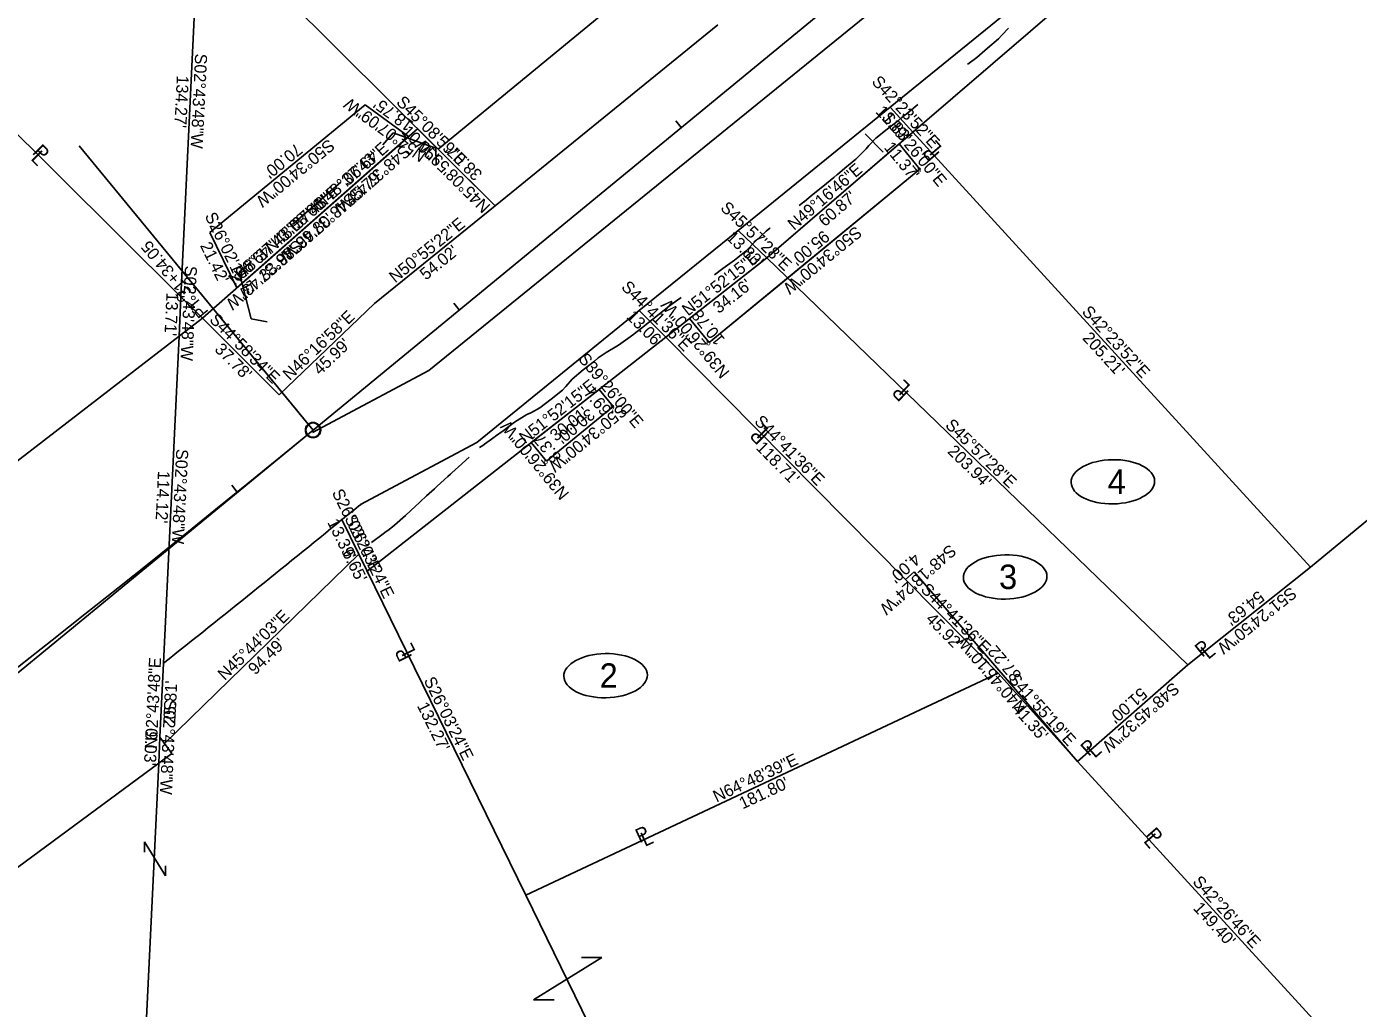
# Model space of a CAD drawing. Extents: x 1145508 to 2262867, y -3126236 to 2021677.
# Drawn here: x 1146740.3 to 1147204, y 2016667.2 to 2017009.2 of the extents above; entities that cross this region are included whole.
import ezdxf

# ---------------------------------------------------------------- set-up
doc = ezdxf.new("R2010")
doc.units = 0
for name, color, linetype in [('Default', 7, 'Continuous'), ('DSN_RDWY_Alignment', 7, 'Continuous'), ('DSN_RDWY_Alignment Annotation', 7, 'Continuous'), ('DSN_RDWY_Const Limits', 7, 'Continuous'), ('DSN_ROW_Annotation', 7, 'Continuous'), ('DSN_ROW_Esmnt', 7, 'Continuous'), ('DSN_ROW_Line', 7, 'Continuous'), ('DSN_ROW_Line-Annotation', 7, 'Continuous'), ('DSN_ROW_Prop-Line', 7, 'Continuous'), ('DSN_ROW_Prop-Line-Annotation', 7, 'Continuous'), ('DSN_ROW_Temp-Esmnt', 7, 'Continuous'), ('E_Const Align', 7, 'Continuous'), ('EX_PRIMARY_CTL', 7, 'Continuous'), ('EX_ROW', 7, 'Continuous'), ('EX_ROW_ANNOT', 7, 'Continuous'), ('EX_SECTION', 7, 'Continuous'), ('EX_SIGN', 7, 'Continuous')]:
    doc.layers.add(name, color=color, linetype=linetype)

msp = doc.modelspace()

# ---------------------------------------------------------------- linework, layer by layer
at = {"layer": 'Default'}
for p, q in [((1147109.89, 2017075.82), (1146880.36, 2016889.44)), ((1146880.36, 2016889.44), (1146839.86, 2016867.83))]:
    msp.add_line(p, q, dxfattribs=at)
at = {"layer": 'DSN_RDWY_Alignment'}
msp.add_line((1146478.89, 2016571.64), (1146840, 2016868.61), dxfattribs=at)
msp.add_lwpolyline([(1146840, 2016868.61), (1146758.6, 2016967.6)], dxfattribs=at)
msp.add_circle((1146840, 2016868.61), 2.5, dxfattribs=at)
at = {"layer": 'DSN_RDWY_Alignment Annotation'}
for p, q in [((1146966.27, 2016976.34), (1146968.17, 2016974.02)), ((1146838.31, 2016870.68), (1146782.84, 2016938.13)), ((1146782.84, 2016938.13), (1146782.84, 2016938.13)), ((1146889.03, 2016912.82), (1146890.94, 2016910.5)), ((1146840, 2016868.61), (1146840, 2016868.61)), ((1146811.74, 2016849.39), (1146813.64, 2016847.06))]:
    msp.add_line(p, q, dxfattribs=at)
msp.add_circle((1146840, 2016868.61), 2.67, dxfattribs=at)
at = {"layer": 'DSN_RDWY_Const Limits'}
for points in [[(1147067.91, 2016996.1), (1147068.3, 2016996.37), (1147068.41, 2016996.45), (1147071.13, 2016998.39), (1147074.88, 2017001.7), (1147078.68, 2017004.95), (1147079.75, 2017006.08), (1147079.84, 2017006.17), (1147082.15, 2017008.6)], [(1147009.31, 2016946.85), (1147009.68, 2016947.16), (1147010.91, 2016948.15), (1147010.96, 2016948.19), (1147013.56, 2016950.31), (1147017.45, 2016953.46), (1147021.31, 2016956.63), (1147022.52, 2016957.64), (1147022.57, 2016957.69), (1147025.15, 2016959.84), (1147028.99, 2016963.04), (1147032.53, 2016966.6), (1147033.54, 2016967.76), (1147033.67, 2016967.91), (1147035.94, 2016970.33), (1147039.86, 2016973.44), (1147043.83, 2016976.48), (1147045, 2016977.58), (1147045.01, 2016977.58), (1147047.71, 2016979.64), (1147050.59, 2016982.09)], [(1146979.79, 2016922.75), (1146982.68, 2016924.89), (1146984.29, 2016926.08), (1146985.94, 2016927.3), (1146986.71, 2016927.87), (1146987.94, 2016928.78), (1146988.07, 2016928.87), (1146990.67, 2016930.92), (1146994.15, 2016934.56), (1146997.82, 2016937.96), (1146999, 2016938.99), (1146999.08, 2016939.06)], [(1146898.02, 2016862.52), (1146899.08, 2016863.29), (1146899.58, 2016863.64), (1146899.59, 2016863.65), (1146899.65, 2016863.69), (1146902.09, 2016865.45), (1146903.07, 2016866.17), (1146903.3, 2016866.33), (1146903.37, 2016866.38), (1146903.52, 2016866.49), (1146906.15, 2016868.39), (1146910.12, 2016871.43), (1146914.44, 2016874.04), (1146915.88, 2016874.68), (1146916.11, 2016874.77), (1146919.02, 2016876.36), (1146922.95, 2016879.44), (1146926.87, 2016882.54), (1146927.89, 2016883.68), (1146928.05, 2016883.86), (1146930.25, 2016886.32), (1146934.02, 2016889.59), (1146937.95, 2016892.69), (1146939.16, 2016893.67), (1146939.27, 2016893.76), (1146942.01, 2016895.63), (1146946.35, 2016898.22), (1146950.46, 2016901.09), (1146951.67, 2016902.01), (1146951.83, 2016902.14), (1146954.41, 2016904.17), (1146958.33, 2016907.26), (1146962.24, 2016910.38), (1146963.43, 2016911.33), (1146963.59, 2016911.45), (1146965.39, 2016912.85), (1146966.2, 2016913.44), (1146968.22, 2016914.8)], [(1146860.37, 2016829.48), (1146864.43, 2016832.47), (1146865.49, 2016833.26), (1146866.06, 2016833.69), (1146867.71, 2016834.91), (1146867.71, 2016834.92), (1146868.42, 2016835.54), (1146872.15, 2016838.88), (1146875.83, 2016842.28), (1146876.79, 2016843.16), (1146877.29, 2016843.62), (1146879.52, 2016845.67), (1146882.3, 2016848.2), (1146883.22, 2016849.04), (1146886.92, 2016852.41), (1146887.88, 2016853.29), (1146888.36, 2016853.73), (1146890.62, 2016855.78), (1146894.32, 2016859.16)]]:
    msp.add_lwpolyline(points, dxfattribs=at)
at = {"layer": 'DSN_ROW_Esmnt'}
for p, q in [((1146876.39, 2016973.63), (1146801.5, 2016907.67)), ((1146876.39, 2016973.63), (1146838.94, 2016940.65)), ((1146903.38, 2016946.78), (1146876.39, 2016973.63)), ((1146861.44, 2016912.73), (1146903.38, 2016946.78)), ((1146838.94, 2016940.65), (1146801.5, 2016907.67)), ((1146828.2, 2016880.94), (1146861.44, 2016912.73)), ((1146801.5, 2016907.67), (1146828.2, 2016880.94))]:
    msp.add_line(p, q, dxfattribs=at)
at = {"layer": 'DSN_ROW_Line'}
for p, q in [((1146883.52, 2016966.54), (1147084.43, 2017131.78)), ((1147048.88, 2016972.43), (1147200.36, 2017102.81)), ((1146801.5, 2016907.67), (1146876.39, 2016973.63)), ((1146876.39, 2016973.63), (1146883.52, 2016966.54)), ((1146997.95, 2016928.59), (1147048.88, 2016972.43)), ((1147051.3, 2016959.52), (1147044.08, 2016968.3)), ((1147004.92, 2016921.37), (1147051.3, 2016959.52)), ((1146962.79, 2016900.99), (1146997.95, 2016928.59)), ((1146977.93, 2016899.18), (1147004.92, 2016921.37)), ((1146971.08, 2016907.5), (1146977.93, 2016899.18)), ((1146858.89, 2016819.44), (1146962.79, 2016900.99)), ((1146944.49, 2016876.86), (1146939.61, 2016882.8)), ((1146921.32, 2016857.81), (1146944.49, 2016876.86)), ((1146916.01, 2016864.27), (1146921.32, 2016857.81)), ((1146788.31, 2016759.46), (1146855.97, 2016825.41)), ((1146855.97, 2016825.41), (1146858.89, 2016819.44))]:
    msp.add_line(p, q, dxfattribs=at)
at = {"layer": 'DSN_ROW_Line-Annotation'}
for centre in [(1147118.48, 2016850.62), (1147080.98, 2016817.47), (1146941.86, 2016783.08)]:
    msp.add_ellipse(centre, major_axis=(14.54, 0.23), ratio=0.529773, dxfattribs=at)
at = {"layer": 'DSN_ROW_Prop-Line'}
for p, q in [((1147040.91, 2016981.16), (1147048.88, 2016972.43)), ((1147048.88, 2016972.43), (1147187.25, 2016820.88)), ((1146988.01, 2016938.21), (1146997.95, 2016928.59)), ((1146997.95, 2016928.59), (1147144.55, 2016786.81)), ((1146953.61, 2016910.27), (1146962.79, 2016900.99)), ((1146962.79, 2016900.99), (1147046.28, 2016816.6)), ((1147187.25, 2016820.88), (1147252.87, 2016874.96)), ((1146850.09, 2016837.44), (1146855.97, 2016825.41)), ((1146855.97, 2016825.41), (1146914.07, 2016706.59)), ((1147049.27, 2016819.26), (1147046.28, 2016816.6)), ((1147106.2, 2016753.19), (1147049.27, 2016819.26)), ((1147187.25, 2016820.88), (1147144.55, 2016786.81)), ((1147046.28, 2016816.6), (1147078.57, 2016783.96)), ((1147144.55, 2016786.81), (1147106.2, 2016753.19)), ((1146914.07, 2016706.59), (1147078.57, 2016783.96)), ((1147078.57, 2016783.96), (1147106.2, 2016753.19)), ((1147106.2, 2016753.19), (1147207.03, 2016642.95)), ((1146914.07, 2016706.59), (1146993.63, 2016543.86))]:
    msp.add_line(p, q, dxfattribs=at)
at = {"layer": 'DSN_ROW_Prop-Line-Annotation'}
for p, q in [((1146781.31, 2016721.64), (1146781.31, 2016725.19)), ((1146781.31, 2016725.19), (1146788.69, 2016713.34)), ((1146788.69, 2016713.34), (1146788.69, 2016716.88)), ((1146940.52, 2016684.89), (1146916.81, 2016670.12)), ((1146933.43, 2016684.89), (1146940.52, 2016684.89)), ((1146916.81, 2016670.12), (1146923.91, 2016670.12))]:
    msp.add_line(p, q, dxfattribs=at)
at = {"layer": 'DSN_ROW_Temp-Esmnt'}
for p, q in [((1146858.11, 2016981.9), (1146804.04, 2016937.44)), ((1146873.3, 2016970.91), (1146858.11, 2016981.9)), ((1146813.45, 2016918.2), (1146873.3, 2016970.91)), ((1146838.94, 2016940.65), (1146873.3, 2016970.91)), ((1146997.95, 2016928.59), (1147044.08, 2016968.3)), ((1147044.08, 2016968.3), (1147051.3, 2016959.52)), ((1147051.3, 2016959.52), (1146977.93, 2016899.18)), ((1146813.45, 2016918.2), (1146838.94, 2016940.65)), ((1146804.04, 2016937.44), (1146813.45, 2016918.2)), ((1146971.08, 2016907.5), (1146997.95, 2016928.59)), ((1146977.93, 2016899.18), (1146971.08, 2016907.5)), ((1146916.01, 2016864.27), (1146939.61, 2016882.8)), ((1146939.61, 2016882.8), (1146944.49, 2016876.86)), ((1146944.49, 2016876.86), (1146921.32, 2016857.81)), ((1146921.32, 2016857.81), (1146916.01, 2016864.27))]:
    msp.add_line(p, q, dxfattribs=at)
at = {"layer": 'E_Const Align'}
msp.add_line((1146840, 2016868.61), (1147825.51, 2017679.08), dxfattribs=at)
msp.add_arc((1143200.69, 2021293.93), 5729.58, 300.103113, 309.43332, dxfattribs=at)
msp.add_arc((1143200.69, 2021293.93), 5729.58, 300.103113, 309.43332, dxfattribs=at)
at = {"layer": 'EX_ROW'}
for p, q in [((1147040.91, 2016981.16), (1147128.8, 2017052.53)), ((1146800.42, 2017049.21), (1146903.38, 2016946.78)), ((1146903.38, 2016946.78), (1146980.95, 2017009.77)), ((1146700.32, 2017008.19), (1146794.02, 2016915.09)), ((1147040.91, 2016981.16), (1146988.01, 2016938.21)), ((1146861.44, 2016912.73), (1146903.38, 2016946.78)), ((1146988.01, 2016938.21), (1146953.61, 2016910.27)), ((1146794.02, 2016915.09), (1146801.5, 2016907.67)), ((1146828.2, 2016880.94), (1146861.44, 2016912.73)), ((1146793.37, 2016901.4), (1146801.5, 2016907.67)), ((1146801.5, 2016907.67), (1146828.2, 2016880.94)), ((1146953.61, 2016910.27), (1146897.03, 2016864.33)), ((1146721.65, 2016846.02), (1146793.37, 2016901.4)), ((1146897.03, 2016864.33), (1146856.59, 2016842.76)), ((1146790.86, 2016756), (1146786.71, 2016761.63)), ((1146786.28, 2016752.61), (1146790.86, 2016756)), ((1146613.11, 2016624.88), (1146786.28, 2016752.61))]:
    msp.add_line(p, q, dxfattribs=at)
for start_param, end_param in [(4.718574, 4.720028), (4.704767, 4.718574)]:
    msp.add_ellipse((1143207.59, 2021298.94), major_axis=(4499.16, 3626.95), ratio=0.996634, start_param=start_param, end_param=end_param, dxfattribs=at)
at = {"layer": 'EX_SECTION'}
for p, q in [((1146800.42, 2017049.21), (1146794.02, 2016915.09)), ((1146794.02, 2016915.09), (1146793.37, 2016901.4)), ((1146793.37, 2016901.4), (1146787.94, 2016787.41)), ((1146786.71, 2016761.63), (1146787.94, 2016787.41)), ((1146786.71, 2016761.63), (1146786.28, 2016752.61)), ((1146786.28, 2016752.61), (1146769.25, 2016395.47))]:
    msp.add_line(p, q, dxfattribs=at)
at = {"layer": 'EX_SIGN'}
for p, q in [((1146864.35, 2016967.96), (1146867.94, 2016972.21)), ((1146867.94, 2016972.21), (1146882.78, 2016966.87)), ((1147032.26, 2016971.89), (1147038.49, 2016965.45)), ((1146882.78, 2016966.87), (1146882.83, 2016961.09)), ((1146832.9, 2016940.29), (1146849.74, 2016955)), ((1146814.32, 2016923.59), (1146818.63, 2016927.31)), ((1146818.49, 2016907.44), (1146814.32, 2016923.59)), ((1146824.05, 2016906.31), (1146818.49, 2016907.44))]:
    msp.add_line(p, q, dxfattribs=at)

# ---------------------------------------------------------------- texts
at = {"layer": 'DSN_RDWY_Alignment Annotation'}
for s, p in [('31+34.05', (1146798.02, 2016916.82)), ('PT', (1146803.77, 2016909.83))]:
    msp.add_text(s, height=4.2, rotation=129.4333, dxfattribs=at).set_placement(p)
at = {"layer": 'DSN_ROW_Annotation'}
for s, rotation, p in [('S42°23\'52"E', 312.3979, (1147034.26, 2016989.78)), ('N54°07\'09"W', 144.1192, (1146879.81, 2016965.09)), ("18.75'", 144.1192, (1146875.3, 2016975.76)), ('S45°08\'59"E', 315.1496, (1146868.7, 2016982.55)), ("11.83'", 312.3979, (1147035.63, 2016979.38)), ('S39°26\'00"E', 309.4333, (1147037.74, 2016977.43)), ("10.05'", 315.1496, (1146870.58, 2016972.22)), ('S50°34\'00"W', 219.4333, (1146845.37, 2016970.26)), ("70.00'", 219.4333, (1146834.13, 2016968.79)), ('N48°37\'43"E', 41.3713, (1146842.73, 2016945.18)), ('S48°37\'43"W', 221.3713, (1146871.6, 2016968.21)), ('N45°08\'59"W', 135.1496, (1146902.06, 2016946.83)), ("11.37'", 309.4333, (1147038.58, 2016966.97)), ("49.90'", 221.3713, (1146860.41, 2016966.36)), ("38.07'", 135.1496, (1146899.26, 2016958.07)), ("45.79'", 41.3713, (1146853.38, 2016946.57)), ('N49°16\'46"E', 40.7207, (1147007.5, 2016938)), ('N48°37\'43"E', 41.3713, (1146825.55, 2016930.05)), ('S48°37\'43"W', 221.3713, (1146852.87, 2016951.72)), ("99.80'", 221.3713, (1146841.69, 2016949.87)), ("60.87'", 40.7207, (1147018.17, 2016939.26)), ('S26°02\'15"E', 296.0375, (1146802.2, 2016943.27)), ("99.80'", 41.3713, (1146836.2, 2016931.44)), ('S45°57\'28"E', 315.9577, (1146981.56, 2016945.7)), ('N48°37\'43"E', 41.3713, (1146812.8, 2016918.83)), ('N50°55\'22"E', 39.0773, (1146868.61, 2016919.7)), ("13.83'", 315.9577, (1146983.57, 2016935.4)), ('S50°34\'00"W', 219.4333, (1147028.91, 2016939.94)), ("95.00'", 219.4333, (1147017.67, 2016938.47)), ("21.42'", 296.0375, (1146800.58, 2016932.91)), ('S48°37\'43"W', 221.3713, (1146834.15, 2016935.23)), ("49.90'", 221.3713, (1146822.97, 2016933.38)), ("33.98'", 41.3713, (1146823.45, 2016920.21)), ("54.02'", 39.0773, (1146879.3, 2016920.66)), ('N51°52\'15"E', 38.1291, (1146970.54, 2016908.22)), ("34.16'", 38.1291, (1146981.25, 2016909)), ('S44°41\'36"E', 314.6934, (1146947.05, 2016918.18)), ('N39°26\'00"W', 129.4333, (1146985.29, 2016888.82)), ('S44°58\'34"E', 314.976, (1146803.64, 2016906.8)), ('N46°16\'58"E', 43.7174, (1146831.87, 2016885.7)), ("13.06'", 314.6934, (1146948.84, 2016907.84)), ("10.78'", 129.4333, (1146983.63, 2016900.28)), ('S42°23\'52"E', 312.3979, (1147107.43, 2016909.64)), ("205.21'", 312.3979, (1147107.65, 2016900.5)), ("37.78'", 314.976, (1146805.48, 2016896.47)), ("45.99'", 43.7174, (1146842.46, 2016887.51)), ('S39°26\'00"E', 309.4333, (1146932.1, 2016893.35)), ('N51°52\'15"E', 38.1291, (1146913.83, 2016863.71)), ("7.69'", 309.4333, (1146934.02, 2016881.57)), ('S50°34\'00"W', 219.4333, (1146947.2, 2016877.93)), ("30.01'", 38.1291, (1146924.54, 2016864.49)), ("30.00'", 219.4333, (1146935.97, 2016876.45)), ('N39°26\'00"W', 129.4333, (1146929.44, 2016846.52)), ('S44°41\'36"E', 314.6934, (1146993.38, 2016871.35)), ('S45°57\'28"E', 315.9577, (1147059.83, 2016870)), ("8.37'", 129.4333, (1146926.7, 2016859.3)), ("118.71'", 314.6934, (1146993.97, 2016862.22)), ("203.94'", 315.9577, (1147060.62, 2016860.89)), ('S26°03\'24"E', 296.0566, (1146846.47, 2016846.88)), ('S26°03\'24"E', 296.0566, (1146850.87, 2016837.88)), ("13.39'", 296.0566, (1146844.86, 2016836.51)), ('S48°18\'24"W', 221.6934, (1147061.64, 2016829.08)), ("6.65'", 296.0566, (1146850.01, 2016825.98)), ("4.00'", 221.6934, (1147049.19, 2016826.03)), ('S44°41\'36"E', 314.6934, (1147051.28, 2016812.83)), ('S51°24\'50"W', 218.5862, (1147180.35, 2016814.23)), ("54.63'", 218.5862, (1147169.09, 2016812.92)), ('N45°44\'03"E', 44.2658, (1146809.29, 2016781.18)), ("45.92'", 314.6934, (1147053.07, 2016802.49)), ("94.49'", 44.2658, (1146819.86, 2016783.09)), ('N40°45\'10"W', 130.7527, (1147088.85, 2016771.96)), ("87.22'", 130.7527, (1147086.92, 2016783.38)), ('S26°03\'24"E', 296.0566, (1146878.46, 2016781.45)), ('S41°55\'19"E', 311.9219, (1147081.86, 2016781.65)), ('S48°45\'32"W', 221.2411, (1147139.33, 2016781.04)), ("51.00'", 221.2411, (1147128.15, 2016779.21)), ("132.27'", 296.0566, (1146876.11, 2016772.62)), ("41.35'", 311.9219, (1147083.15, 2016771.24)), ('N64°48\'39"E', 25.1891, (1146980.5, 2016738.83)), ("181.80'", 25.1891, (1146989.57, 2016736.46)), ('S42°26\'46"E', 312.4461, (1147145.97, 2016711.05)), ("149.40'", 312.4461, (1147146.2, 2016701.9))]:
    msp.add_text(s, height=4.2, rotation=rotation, dxfattribs=at).set_placement(p)
at = {"layer": 'DSN_ROW_Esmnt'}
for p in [(1147050.3, 2016958.52), (1146976.93, 2016898.18), (1146943.49, 2016875.86), (1146920.32, 2016856.81)]:
    msp.add_text('b', height=2, dxfattribs=at).set_placement(p)
at = {"layer": 'DSN_ROW_Line-Annotation'}
for s, p in [('4', (1147116.66, 2016846.41)), ('3', (1147078.85, 2016813.27)), ('2', (1146939.78, 2016778.87))]:
    msp.add_text(s, height=8.5, dxfattribs=at).set_placement(p)
at = {"layer": 'DSN_ROW_Prop-Line-Annotation'}
for s, rotation, p in [('P', 314.6756, (1146742.01, 2016965.16)), ('L', 130.8619, (1147059.21, 2016967.1)), ('L', 314.6756, (1146741.47, 2016962.99)), ('P', 130.8619, (1147058.52, 2016964.96)), ('L', 136.4729, (1147048.31, 2016883.99)), ('P', 136.4729, (1147047.84, 2016881.8)), ('L', 134.8665, (1146998.89, 2016868.81)), ('P', 134.8665, (1146998.35, 2016866.63)), ('P', 116.6565, (1146874.68, 2016789.63)), ('L', 116.6565, (1146875.87, 2016791.53)), ('P', 39.1563, (1147149.58, 2016789.28)), ('L', 39.1563, (1147151.69, 2016788.53)), ('P', 41.65, (1147110.01, 2016754.77)), ('L', 41.65, (1147112.16, 2016754.11)), ('P', 24.5585, (1146953.68, 2016724.65)), ('L', 24.5585, (1146955.53, 2016723.39)), ('L', 310.8619, (1147128.9, 2016725.35)), ('P', 310.8619, (1147129.59, 2016727.49))]:
    msp.add_text(s, height=5, rotation=rotation, dxfattribs=at).set_placement(p)
at = {"layer": 'EX_PRIMARY_CTL'}
msp.add_text('C', height=3.5, dxfattribs=at).set_placement((1146792.27, 2016913.34))
at = {"layer": 'EX_ROW_ANNOT'}
for s, rotation, p in [('S02°43\'48"W', 267.27, (1146798.97, 2016999.86)), ('S02°43\'48"W', 267.27, (1146798.97, 2016999.86)), ("134.27'", 267.27, (1146792.6, 2016992.24)), ("134.27'", 267.27, (1146792.6, 2016992.24)), ('S02°43\'48"W', 267.27, (1146795.44, 2016925.95)), ('S02°43\'48"W', 267.27, (1146795.44, 2016925.95)), ("13.71'", 267.27, (1146788.99, 2016916.63)), ("13.71'", 267.27, (1146788.99, 2016916.63)), ('S02°43\'48"W', 267.27, (1146792.4, 2016862.11)), ('S02°43\'48"W', 267.27, (1146792.4, 2016862.11)), ("114.12'", 267.27, (1146786.03, 2016854.49)), ("114.12'", 267.27, (1146786.03, 2016854.49)), ('N02°43\'48"E', 87.27, (1146785.61, 2016757.53)), ('N02°43\'48"E', 87.27, (1146785.61, 2016757.53)), ("25.81'", 87.27, (1146792.03, 2016766.13)), ("25.81'", 87.27, (1146792.03, 2016766.13)), ('S02°43\'48"W', 267.27, (1146788.24, 2016774.83)), ('S02°43\'48"W', 267.27, (1146788.24, 2016774.83)), ("9.03'", 267.27, (1146781.7, 2016763.8)), ("9.03'", 267.27, (1146781.7, 2016763.8))]:
    msp.add_text(s, height=4.2, rotation=rotation, dxfattribs=at).set_placement(p)

doc.saveas('drawing.dxf')
